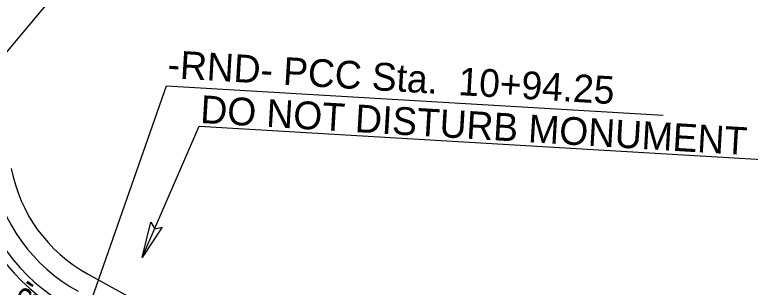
# Model space of a CAD drawing. Extents: x 2010838 to 2015151, y 441905 to 447792.
# Drawn here: x 2013251.3 to 2013436.5, y 444988.3 to 445057.1 of the extents above; entities that cross this region are included whole.
import ezdxf

# ---------------------------------------------------------------- set-up
doc = ezdxf.new("R2010")
doc.units = 0
for name, color, linetype in [('C-Grave Plots', 7, 'Continuous'), ('C-Profile', 7, 'Continuous'), ('CLRD', 7, 'Continuous'), ('Default_10ft_LIDAR_Contou', 7, 'Continuous'), ('HATCH', 7, 'Continuous'), ('s-Existing Major', 7, 'Continuous'), ('S-Existing Minor', 7, 'Continuous'), ('S-overhead electric', 7, 'Continuous'), ('TEXT-LG', 7, 'Continuous'), ('TEXT-MED', 7, 'Continuous')]:
    doc.layers.add(name, color=color, linetype=linetype)

msp = doc.modelspace()

# ---------------------------------------------------------------- linework, layer by layer
at = {"layer": 'C-Profile'}
msp.add_arc((2013223.9, 446217.91), 1306.75, 277.85834, 301.87193, dxfattribs=at)
at = {"layer": 'CLRD'}
for centre, radius, start, end in [((2013223.9, 446217.91), 1300, 266.62643, 322.2051), ((2013818.28, 444917.2), 630, 153.45572, 179.8908)]:
    msp.add_arc(centre, radius, start, end, dxfattribs=at)
at = {"layer": 'Default_10ft_LIDAR_Contou'}
for p, q in [((2013191.25, 444978.32), (2013276.3, 445079.96)), ((2013248.22, 444921), (2013289.46, 445039.08)), ((2013289.46, 445039.08), (2013414.48, 445031.71))]:
    msp.add_line(p, q, dxfattribs=at)
at = {"layer": 'HATCH'}
msp.add_circle((2013188.28, 444918.4), 75, dxfattribs=at)
msp.add_arc((2013223.9, 446217.91), 1320.75, 278.35841, 312.84627, dxfattribs=at)
at = {"layer": 's-Existing Major'}
msp.add_lwpolyline([(2013288.38, 445003.48), (2013283.39, 444995.83), (2013285.51, 445004.77), (2013286.52, 445003.08)], close=True, dxfattribs=at)
at = {"layer": 'S-Existing Minor'}
for p, q in [((2013283.39, 444995.83), (2013297.69, 445028.91)), ((2013297.69, 445028.91), (2013441.62, 445020.43))]:
    msp.add_line(p, q, dxfattribs=at)
at = {"layer": 'S-overhead electric'}
for centre, radius, start, end in [((2013223.9, 446217.91), 1308.75, 277.85834, 301.87193), ((2013288.24, 445025.39), 50, 190.6549, 241.0711)]:
    msp.add_arc(centre, radius, start, end, dxfattribs=at)
at = {"layer": 'TEXT-LG'}
msp.add_line((2013269.62, 444991.7), (2013296.59, 444976.79), dxfattribs=at)
for centre, radius, start, end in [((2013288.24, 445025.39), 38.5, 190.6549, 241.0711), ((2013288.24, 445025.39), 43.5, 190.6549, 241.0711), ((2013842.57, 443569.75), 1472.5, 104.09144, 108.18835), ((2013842.57, 443569.75), 1467.5, 104.39059, 108.18835)]:
    msp.add_arc(centre, radius, start, end, dxfattribs=at)
at = {"layer": 'TEXT-MED'}
msp.add_arc((2013288.24, 445025.39), 48, 190.6549, 241.0711, dxfattribs=at)

# ---------------------------------------------------------------- texts
at = {"layer": 'C-Grave Plots'}
msp.add_text("13.3'", height=6, rotation=55.581, dxfattribs=at).set_placement((2013250, 444972.78))
at = {"layer": 'Default_10ft_LIDAR_Contou'}
msp.add_text('-RND- PCC Sta.  10+94.25', height=7, rotation=356.6264, dxfattribs=at).set_placement((2013289.62, 445041.11))
at = {"layer": 'S-Existing Minor'}
msp.add_text('DO NOT DISTURB MONUMENT', height=7, rotation=356.6264, dxfattribs=at).set_placement((2013297.86, 445029.76))

doc.saveas('drawing.dxf')
